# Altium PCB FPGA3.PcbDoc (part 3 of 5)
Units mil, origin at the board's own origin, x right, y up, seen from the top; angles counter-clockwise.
Board outline 4000 x 2750 mil, 12 copper layers (Top Layer, Plane1, MidLayer1, Plane2, MidLayer2, Plane3, Plane4, MidLayer 3, Plane5, MidLayer 4, Plane6, Bottom Layer), stack 57.29 mil thick; 420 components, 368 nets, 1889 pads, 1236 vias.
Unrouted connection lines stored in the file: 1.
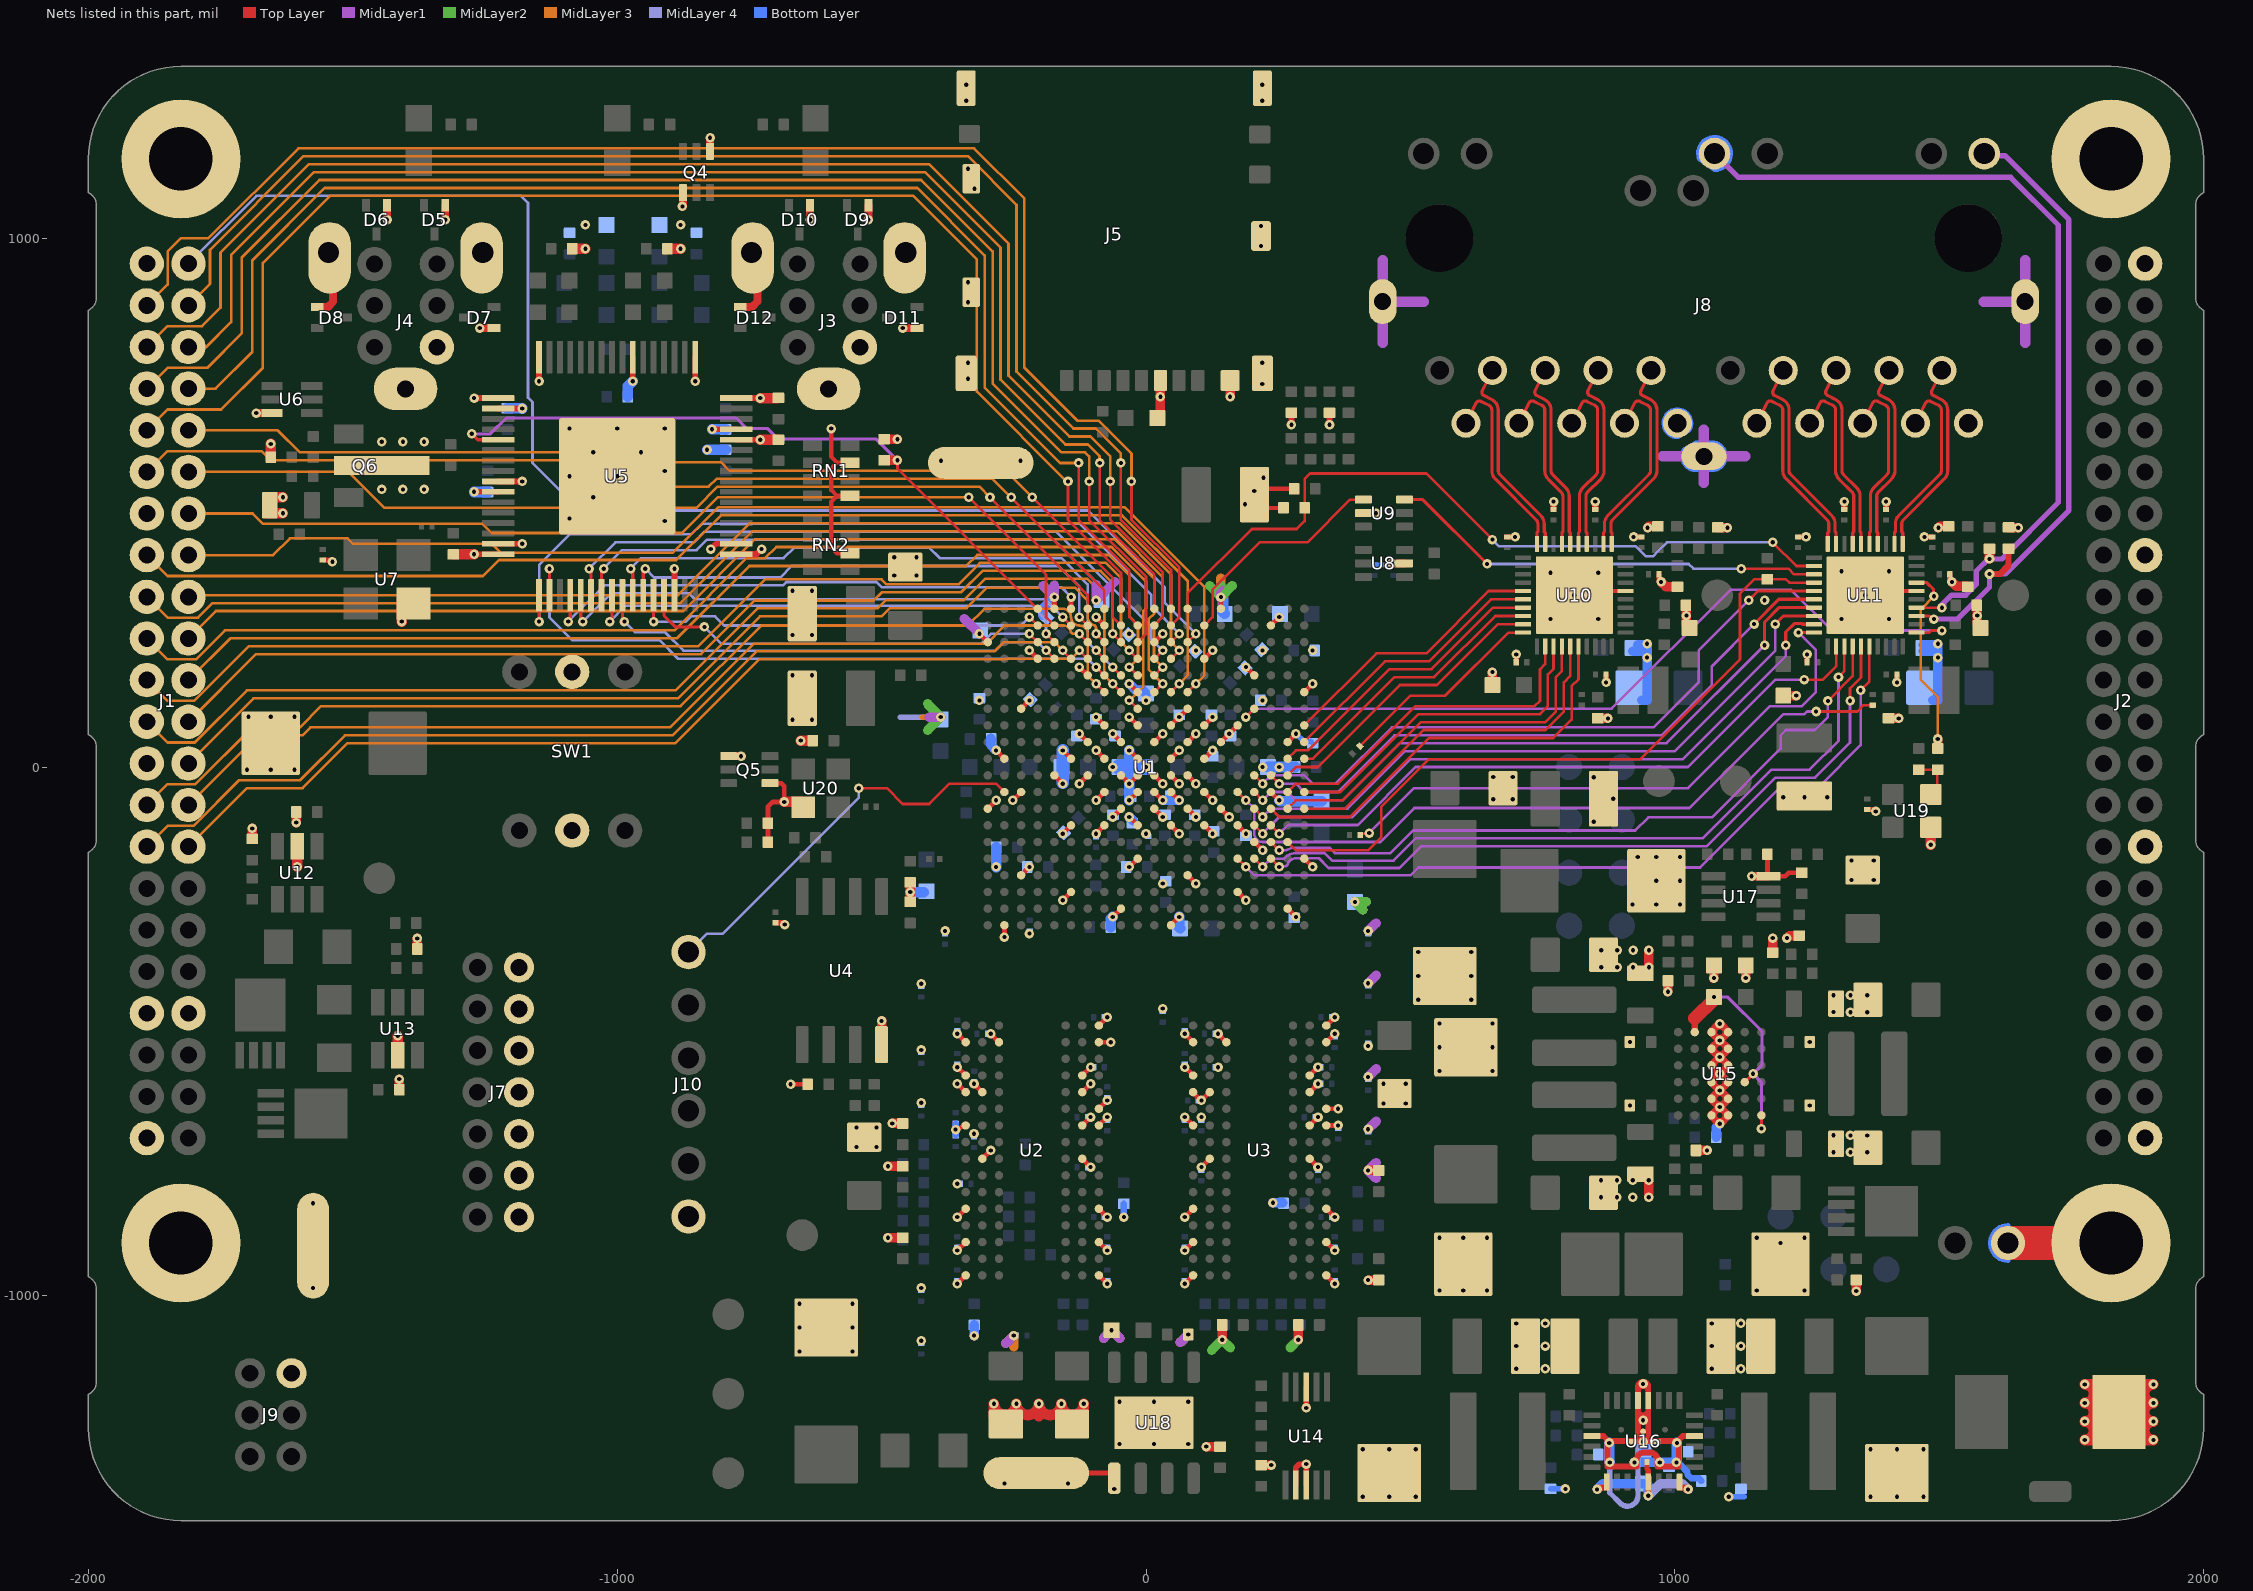
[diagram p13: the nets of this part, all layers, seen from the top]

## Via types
v1: diameter 18, hole 8, Top Layer to Bottom Layer, tented both sides, 1236 vias

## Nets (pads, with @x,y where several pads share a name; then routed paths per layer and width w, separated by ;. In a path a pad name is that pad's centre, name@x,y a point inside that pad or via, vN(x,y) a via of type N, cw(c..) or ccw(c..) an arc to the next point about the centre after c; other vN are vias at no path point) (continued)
e1-RxD0_5: U1.Y8 U10.25 | length 694.9
  Top Layer w5: U1.Y8@299.21,-78.74 376.26,-78.74 525,70 755,70 790,105 790,160 802.13,172.13 U10.25@802.13,228
e1-RxD1_5: U1.W8 U10.24 | length 711.1
  Top Layer w5: U1.W8@267.72,-78.74 283.46,-62.99 372.01,-62.99 520,85 755,85 775,105 775,170 786.38,181.38 U10.24@786.38,228
e1-RxD2_5: U1.Y9 U10.23 | length 645.4
  Top Layer w5: U1.Y9@299.21,-47.24 367.76,-47.24 515,100 745,100 760,115 760,175 770.63,185.63 U10.23@770.63,228
e1-RxD3_5: U1.W9 U10.22 | length 655.7
  Top Layer w5: U1.W9@267.72,-47.24 283.46,-31.5 363.5,-31.5 510,115 735,115 745,125 745,184.82 754.88,194.71 U10.22@754.88,228
e1-RxVAL_5: U1.V8 U10.26 | length 795.1
  Top Layer w5: U1.V8@236.22,-78.74 251.97,-94.49 385.51,-94.49 535,55 770,55 805,90 805,152.77 817.87,165.65 U10.26@817.87,228
e1-TxCLK_5: R1.2 U10.20 | length 397.3
  Top Layer w5: R1.2@404.57,39.57 500,135 565.87,135 685,254.13 U10.20@713,254.13
e1-TxD0_5: U1.Y11 U10.18 | length 525.6
  Top Layer w5: U1.Y11@299.21,15.75 315.75,15.75 470,170 545,170 660.63,285.63 U10.18@713,285.63
e1-TxD1_5: U1.W11 U10.17 | length 563.6
  Top Layer w5: U1.W11@267.72,15.75 283.47,31.5 306.5,31.5 460,185 540,185 656.38,301.38 U10.17@713,301.38
e1-TxD2_5: U1.Y12 U10.16 | length 525.6
  Top Layer w5: U1.Y12@299.21,47.24 451.97,200 535,200 652.13,317.13 U10.16@713,317.13
e1-TxD3_5: U1.Y13 U10.15 | length 519.1
  Top Layer w5: U1.Y13@299.21,78.74 435.47,215 530,215 647.87,332.87 U10.15@713,332.87
e1-TxEN_5: U1.W10 U10.19 | length 563.6
  Top Layer w5: U1.W10@267.72,-15.75 283.46,0 325,0 480,155 550,155 664.88,269.88 U10.19@713,269.88
e2-/IRQ: U1.U14 U11.31 | length 1519.4
  Top Layer w5: v1(188.98,94.49) U1.U14@204.72,110.24 ; U11.31@1457,254.13 1481.13,254.13 1485.13,258.13 v1(1505,258.13)
  MidLayer1 w5: v1(188.98,94.49) 204.72,110.24 880.24,110.24 1105,335 1220,335 1296.87,258.13 v1(1505,258.13)
e2-/RESET: R59.1 U1.N20 U11.12 | length 1449
  Top Layer w5: U1.N20@78.74,299.21 78.74,328.74 200,450 285,450 300,465 R59.1@300,490 300,545 310,555 530,555 v1(655,430) ; v1(1185,425) 1229.88,380.12 U11.12@1263,380.12
  MidLayer 4 w5: v1(655,430) 667.63,417.37 926.3,417.37 945.17,398.5 958.83,398.5 968.5,408.17 968.5,408.5 985,425 v1(1185,425)
e2-CLK25_5: R39.2 U11.37 | length 361.2
  Top Layer w6: U11.37@1457,348.62 1476.38,348.62 1489.27,335.73 v1@1489.27,323.73
  Top Layer w18: R39.2@1497,35 v1(1497,53)
  MidLayer 3 w5: v1(1490,323) 1465,298 1465,165 1497,133 v1(1497,53)
e2-LED1_5: J8.11B R71.2 U11.33 | length 1227.7
  Top Layer w5: U11.33@1457,285.63 1480.61,285.63 v1(1490,279.76)
  Top Layer w12: v1(1595,365) 1615,365 1631,381 R71.2@1631,413 ; R71.2@1630,413 R71.2@1630,415
  MidLayer1 w10: v1(1490,279.76) 1534.76,279.76 1595,340 v1(1595,365) 1625,365 1745,485 1745,1035 1624,1156 1589,1156 J8.11B@1585,1160
e2-LED2_5: J8.14B R70.2 U11.34 | length 1814.1
  Top Layer w5: U11.34@1457,301.38 v1(1505,301.38)
  Top Layer w18: v1(1595,393.5) R70.2@1595,413
  MidLayer1 w10: J8.14B@1075,1160 1120,1115 1635,1115 1725,1025 1725,500 1618.5,393.5 v1(1595,393.5) ; v1@1502.17,304.21 1509,311.03 ; v1@1509,301.38 1509,311.03 ; v1@1595,395.5 1570,370.5 1570,345 1550,325 1522.97,325 1517.3,319.34 1509,311.03
  Bottom Layer w10: 1046.81,1149.74 cw(c1075,1160) 1075,1130 1046.81,1149.78
e2-MDIO-C: U1.P19 U9.1 | length 430.1
  Top Layer w5: U1.P19@110.24,267.72 125.98,283.46 125.98,335.98 215,425 305,425 385.59,505.59 U9.1@411,505.59
e2-MDIO-C/1.8_5: U9.6 U11.13 | length 832.5
  Top Layer w5: v1(1125.5,375) 1215,375 1225.63,364.37 U11.13@1263,364.37
  Top Layer w6: U9.6@489,505.59 523.41,505.59 v1(645,384)
  MidLayer 4 w5: v1(645,384) 1026,384 1035,375 v1(1125.5,375)
e2-MDIO-D/1.8_5: R63.1 U1.W6 U11.14 | length 1323.6
  Top Layer w5: U1.W6@267.72,-141.73 283.46,-157.48 420.02,-157.48 445,-132.5 445,-75 535,15 935,15 1123.23,203.23 1123.23,328.23 1150,355 R63.1@1175,355 1210,355 1216.38,348.62 U11.14@1263,348.62
e2-RxCLK_5: R4.1 U1.T9 | length 1380.8
  Top Layer w5: U1.T9@173.23,-47.24 v1(188.98,-62.99) ; v1@1264.73,105.28 v1@1267.23,102.78 ; v1(1267,105) 1345,105 1357,117 R4.1@1374,117
  MidLayer1 w5: v1(188.98,-62.99) 204.72,-78.74 204.72,-125.98 ccw(c220.47,-125.98) 220.47,-141.73 443.27,-141.73 507.5,-77.5 1027.5,-77.5 1205,100 1245,100 1250,105 v1(1267,105)
e2-RxD0_5: U1.V5 U11.25 | length 1403.3
  Top Layer w5: U1.V5@236.22,-173.23 v1(251.97,-188.98) ; v1(1331.23,125.38) 1331.23,148.72 1352.13,169.61 U11.25@1352.13,228
  MidLayer1 w5: v1@253.22,-187.94 261.39,-187.94 ccw(c261.39,-180.94) 267.96,-183.33 cw(c283.47,-188.98) 283.47,-172.48 327,-172.48 345.52,-191 479,-191 520,-150 1060,-150 1190,-20 1265,-20 1331.23,46.23 v1(1331.23,125.38)
e2-RxD1_5: U1.V6 U11.24 | length 1339.3
  Top Layer w5: U1.V6@236.22,-141.73 v1(251.97,-157.48) ; v1(1289.45,125) 1336.38,171.93 U11.24@1336.38,228
  MidLayer1 w5: v1(251.97,-157.48) 265.03,-157.48 cw(c283.47,-188.98) 283.46,-152.48 346.74,-152.48 357.26,-163 462,-163 505,-120 925,-120 950,-95 1070,-95 1200,35 1200,60 1210,70 1265,70 1289.45,94.45 v1(1289.45,125)
e2-RxD2_5: U1.U5 U11.23 | length 1404.1
  Top Layer w5: U1.U5@204.72,-173.23 v1(220.47,-188.98) ; v1(1309.45,170) 1320.63,181.18 U11.23@1320.63,228
  MidLayer1 w5: v1(220.47,-188.98) 236.22,-173.23 261.74,-173.23 264.73,-170.24 cw(c283.47,-188.98) 283.47,-162.48 337.48,-162.48 352,-177 468,-177 510,-135 1052.5,-135 1182.5,-5 1255,-5 1309.45,49.45 v1(1309.45,170)
e2-RxD3_5: U1.V7 U11.22 | length 1243.8
  Top Layer w5: U1.V7@236.22,-110.24 v1(251.97,-125.98) ; v1(1244.73,165.28) 1279.73,165.28 1304.88,190.43 U11.22@1304.88,228
  MidLayer1 w5: v1(251.97,-125.98) 268.46,-109.49 400.51,-109.49 510,0 1025,0 1190.28,165.28 v1(1244.73,165.28)
e2-RxVAL_5: U1.T5 U11.26 | length 1486.6
  Top Layer w5: U1.T5@173.23,-173.23 v1(188.98,-188.98) ; v1(1351.23,145.38) 1367.87,162.03 U11.26@1367.87,228
  MidLayer1 w5: v1(188.98,-188.98) 204.73,-204.72 500.28,-204.72 515,-190 1048,-190 1203,-35 1275,-35 1351.23,41.23 v1(1351.23,145.38)
e2-TxCLK_5: R2.2 U11.20 | length 1126.3
  Top Layer w5: R2.2@405,-125.98 v1@420.75,-125.98
  Top Layer w6: v1(1233.58,254.13) U11.20@1263,254.13
  MidLayer1 w5: v1(422,-125) 507,-40 1025,-40 1180,115 1240,115 1266.5,141.5 1266.5,221.22 v1(1233.58,254.13)
e2-TxD0_5: U1.U8 U11.18 | length 1251.9
  Top Layer w5: U1.U8@204.72,-78.74 v1(220.47,-94.49)
  Top Layer w6: v1(1189.73,270.28) 1205.08,285.63 U11.18@1263,285.63
  MidLayer1 w5: v1(220.47,-94.49) 236.22,-78.74 381.26,-78.74 490,30 1000,30 1189.73,219.73 v1(1189.73,270.28)
e2-TxD1_5: U1.U9 U11.17 | length 1254.6
  Top Layer w5: U1.U9@204.72,-47.24 v1(220.47,-62.99)
  Top Layer w6: v1(1169.73,230.28) 1169.73,274.32 1196.79,301.38 U11.17@1263,301.38
  MidLayer1 w5: v1(220.47,-62.99) 236.22,-47.24 267.72,-47.24 283.46,-62.99 372.01,-62.99 480,45 984.45,45 v1(1169.73,230.28)
e2-TxD2_5: U1.V10 U11.16 | length 1211.6
  Top Layer w5: U1.V10@236.22,-15.75 v1(251.97,-31.5)
  Top Layer w6: v1(1149.73,270.28) 1196.58,317.13 U11.16@1263,317.13
  MidLayer1 w5: v1(251.97,-31.5) 283.46,-31.5 299.21,-47.24 362.76,-47.24 470,60 975,60 1070,155 1070,190.55 v1(1149.73,270.28)
e2-TxD3_5: U1.U10 U11.15 | length 1264.2
  Top Layer w5: U1.U10@204.72,-15.75 v1(220.47,-31.5)
  Top Layer w6: v1(1139.73,315.28) 1157.32,332.87 U11.15@1263,332.87
  MidLayer1 w5: v1(220.47,-31.5) 236.22,-15.75 299.28,-15.75 314.98,-31.45 358.55,-31.45 465,75 960,75 1045,160 1045,220.55 v1(1139.73,315.28)
e2-TxEN_5: U1.U7 U11.19 | length 1256.5
  Top Layer w5: U1.U7@204.72,-110.24 v1(220.47,-125.98)
  Top Layer w6: v1(1209.73,230.28) 1209.73,255.28 1225.58,271.13 1240.63,271.13 1241.88,269.88 U11.19@1263,269.88
  MidLayer1 w5: v1(220.47,-125.98) 251.97,-94.49 390.51,-94.49 500,15 1015,15 1209.73,209.73 v1(1209.73,230.28)
e-CLK25_5: R38.1 R39.1 U19.3 | length 93.5
  Top Layer w5: R38.1@1461,-5 1496,-5 U19.3@1496,-55 ; U19.3@1484,-52 U19.3@1486,-50
  Top Layer w11: U19.3@1484,-52 U19.3@1488,-48
ETH1-A+_5: J8.2A U10.1 | length 383.5
  Top Layer w6: U10.1@880.87,422 880.87,443.13 878.99,445 878.99,460 cw(c888.99,460) 881.92,467.07 959.6,544.75 ccw(c944,560.26) 966,560.26 966,675.1 ccw(c944,675.1) 953.84,694.78 938.94,702.24 cw(c942.07,708.5) 935.81,711.63 J8.2A@955,750
ETH1-A-_5: J8.3A U10.2 | length 370.2
  Top Layer w6: U10.2@865.12,422 865.12,443.13 866.99,445 866.99,460 cw(c888.99,460) 873.4,475.52 ; J8.3A@905,650 924.19,688.37 cw(c930.45,685.24) 933.58,691.5 948.47,684.04 cw(c944,675.1) 954,675.1 954,560.26 cw(c944,560.26) 951.07,553.19 873.44,475.56 ; 873.4,475.52 cw(c888.99,460) 873.44,475.56 ; 873.4,475.52 873.44,475.56
ETH1-B+_5: J8.4A U10.4 | length 361.6
  Top Layer w6: U10.4@833.62,422 833.62,443.13 831.75,445 831.75,512.49 cw(c841.75,512.49) 834.68,519.56 859.6,544.48 ccw(c844,560) 866,560 866,675.1 ccw(c844,675.1) 853.84,694.78 838.94,702.24 cw(c842.07,708.5) 835.81,711.63 J8.4A@855,750
ETH1-B-_5: J8.5A U10.5 | length 348.3
  Top Layer w6: J8.5A@805,650 824.19,688.37 cw(c830.45,685.24) 833.58,691.5 848.47,684.04 cw(c844,675.1) 854,675.1 854,560 cw(c844,560) 851.07,552.93 826.15,528.01 ccw(c841.75,512.49) 819.75,512.49 819.75,445 817.87,443.13 U10.5@817.87,422
ETH1-C+_5: J8.6A U10.6 | length 361.6
  Top Layer w6: J8.6A@755,750 735.81,711.63 ccw(c742.07,708.5) 738.94,702.24 753.84,694.78 cw(c744,675.1) 766,675.1 766,560 ccw(c776,560) 768.93,552.93 793.85,528.01 cw(c778.25,512.49) 800.25,512.49 800.25,445 802.13,443.13 U10.6@802.13,422
ETH1-C-_5: J8.7A U10.7 | length 348.3
  Top Layer w6: J8.7A@705,650 724.19,688.37 cw(c730.45,685.24) 733.58,691.5 748.47,684.04 cw(c744,675.1) 754,675.1 754,560 ccw(c776,560) 760.4,544.48 785.32,519.56 cw(c778.25,512.49) 788.25,512.49 788.25,445 786.38,443.13 U10.7@786.38,422
ETH1-D+_5: J8.8A U10.9 | length 383.4
  Top Layer w6: J8.8A@655,750 635.81,711.63 ccw(c642.07,708.5) 638.94,702.24 653.84,694.78 cw(c644,675.1) 666,675.1 666,560.26 ccw(c676,560.26) 668.93,553.19 746.56,475.56 ; 746.6,475.52 cw(c731.01,460) 753.01,460 753.01,445 754.88,443.13 U10.9@754.88,422
ETH1-D-_5: J8.9A U10.10 | length 370.2
  Top Layer w6: J8.9A@605,650 624.19,688.37 cw(c630.45,685.24) 633.58,691.5 648.47,684.04 cw(c644,675.1) 654,675.1 654,560.26 ccw(c676,560.26) 660.4,544.75 738.08,467.07 cw(c731.01,460) 741.01,460 741.01,445 739.13,443.13 U10.10@739.13,422
ETH2-A+_5: J8.2B U11.1 | length 383.5
  Top Layer w6: U11.1@1430.87,422 1430.87,443.13 1428.99,445 1428.99,460 cw(c1438.99,460) 1431.92,467.07 1509.6,544.75 ccw(c1494,560.26) 1516,560.26 1516,675.1 ccw(c1494,675.1) 1503.84,694.78 1488.94,702.24 cw(c1492.07,708.5) 1485.81,711.63 J8.2B@1505,750
ETH2-A-_5: J8.3B U11.2 | length 370.2
  Top Layer w6: U11.2@1415.12,422 1415.12,443.13 1416.99,445 1416.99,460 cw(c1438.99,460) 1423.4,475.52 ; J8.3B@1455,650 1474.19,688.37 cw(c1480.45,685.24) 1483.58,691.5 1498.47,684.04 cw(c1494,675.1) 1504,675.1 1504,560.26 cw(c1494,560.26) 1501.07,553.19 1423.44,475.56 ; 1423.4,475.52 cw(c1438.99,460) 1423.44,475.56 ; 1423.4,475.52 1423.44,475.56
ETH2-B+_5: J8.4B U11.4 | length 361.6
  Top Layer w6: U11.4@1383.62,422 1383.62,443.13 1381.75,445 1381.75,512.49 cw(c1391.75,512.49) 1384.68,519.56 1409.6,544.48 ccw(c1394,560) 1416,560 1416,675.1 ccw(c1394,675.1) 1403.84,694.78 1388.94,702.24 cw(c1392.07,708.5) 1385.81,711.63 J8.4B@1405,750
ETH2-B-_5: J8.5B U11.5 | length 348.3
  Top Layer w6: J8.5B@1355,650 1374.19,688.37 cw(c1380.45,685.24) 1383.58,691.5 1398.47,684.04 cw(c1394,675.1) 1404,675.1 1404,560 cw(c1394,560) 1401.07,552.93 1376.15,528.01 ccw(c1391.75,512.49) 1369.75,512.49 1369.75,445 1367.87,443.13 U11.5@1367.87,422
ETH2-C+_5: J8.6B U11.6 | length 361.6
  Top Layer w6: J8.6B@1305,750 1285.81,711.63 ccw(c1292.07,708.5) 1288.94,702.24 1303.84,694.78 cw(c1294,675.1) 1316,675.1 1316,560 ccw(c1326,560) 1318.93,552.93 1343.85,528.01 cw(c1328.25,512.49) 1350.25,512.49 1350.25,445 1352.13,443.13 U11.6@1352.13,422
ETH2-C-_5: J8.7B U11.7 | length 348.3
  Top Layer w6: J8.7B@1255,650 1274.19,688.37 cw(c1280.45,685.24) 1283.58,691.5 1298.47,684.04 cw(c1294,675.1) 1304,675.1 1304,560 ccw(c1326,560) 1310.4,544.48 1335.32,519.56 cw(c1328.25,512.49) 1338.25,512.49 1338.25,445 1336.38,443.13 U11.7@1336.38,422
ETH2-D+_5: J8.8B U11.9 | length 383.4
  Top Layer w6: J8.8B@1205,750 1185.81,711.63 ccw(c1192.07,708.5) 1188.94,702.24 1203.84,694.78 cw(c1194,675.1) 1216,675.1 1216,560.26 ccw(c1226,560.26) 1218.93,553.19 1296.56,475.56 ; 1296.6,475.52 cw(c1281.01,460) 1303.01,460 1303.01,445 1304.88,443.13 U11.9@1304.88,422
ETH2-D-_5: J8.9B U11.10 | length 370.2
  Top Layer w6: J8.9B@1155,650 1174.19,688.37 cw(c1180.45,685.24) 1183.58,691.5 1198.47,684.04 cw(c1194,675.1) 1204,675.1 1204,560.26 ccw(c1226,560.26) 1210.4,544.75 1288.08,467.07 cw(c1281.01,460) 1291.01,460 1291.01,445 1289.13,443.13 U11.10@1289.13,422
FW-/RST: R83.1 U1.D20 U5.53 | length 1320.8
  Top Layer w5: v1(-470,580) -470,564.49 U1.D20@-204.72,299.21
  Top Layer w6: v1(-1275,630) -1263.9,618.9 U5.53@-1225,618.9
  Top Layer w18: R83.1@-495,580 v1(-470,580)
  MidLayer1 w6: v1(-1275,630) -1240,630 -1210,660 -775,660 -755,640 -715,640 -695,620 -510,620 v1(-470,580)
FW-CLK: U1.H16 U5.2 | length 1236.7
  Top Layer w5: v1(-94.49,188.98) U1.H16@-78.74,173.23
  Top Layer w6: U5.2@-1127.95,325 v1(-1127.95,375)
  MidLayer 4 w5: v1(-1127.95,375) -1127.95,282.95 -1085,240 -920,240 -884.75,204.75 -110.26,204.75 v1(-94.49,188.98)
FW-CTL0: U1.F20 U5.4 | length 1067.7
  Top Layer w6: v1(-1092.58,275) -1088.58,279 U5.4@-1088.58,325
  Top Layer w9: U1.F20@-141.73,299.21 v1(-141.73,321.48)
  MidLayer 4 w5: v1(-1092.58,275) -1024.08,343.5 -686.5,343.5 -680,350 -510,350 -500,340 -160.25,340 v1(-141.73,321.48)
FW-CTL1: U1.F19 U5.5 | length 1022.2
  Top Layer w5: v1(-157.48,283.46) U1.F19@-141.73,267.72
  Top Layer w6: U5.5@-1068.9,325 -1068.9,279 v1(-1064.9,275)
  MidLayer 4 w5: v1(-1064.9,275) -1011.4,328.5 -864,328.5 -852.5,317 -191.02,317 v1(-157.48,283.46)
FW-D0: U1.L17 U5.6 | length 1294.1
  Top Layer w5: U1.L17@15.75,204.72 v1(31.5,220.47)
  Top Layer w6: v1(-1053.21,375) -1049.21,371 U5.6@-1049.21,325
  MidLayer 4 w5: v1(-1053.21,375) -1003.21,425 -855,425 -835,445 -170,445 10,265 10,241.97 v1(31.5,220.47)
FW-D1: U1.J16 U5.7 | length 1234.7
  Top Layer w5: v1(-62.99,188.98) U1.J16@-47.24,173.23
  Top Layer w6: U5.7@-1029.53,325 -1029.53,371 v1(-1025.53,375)
  MidLayer 4 w5: v1(-1025.53,375) -990.53,410 -850,410 -830,430 -175,430 -78.74,333.74 -78.74,204.72 v1(-62.99,188.98)
FW-D2: U1.E18 U5.8 | length 948.4
  Top Layer w5: v1(-188.98,251.97) U1.E18@-173.23,236.22
  Top Layer w6: v1(-1013.84,275) -1009.84,279 U5.8@-1009.84,325
  MidLayer 4 w5: v1(-1013.84,275) -983.84,305 -216,305 -188.98,277.97 v1(-188.98,251.97)
FW-D3: U1.E17 U5.9 | length 907.1
  Top Layer w5: v1(-188.98,220.47) U1.E17@-173.23,204.72
  Top Layer w6: U5.9@-990.16,325 -990.16,279 v1(-986.16,275)
  MidLayer 4 w5: v1(-986.16,275) -966.16,255 -910,255 -875,220 -285,220 -268.78,236.22 -204.72,236.22 v1(-188.98,220.47)
FW-D4: U1.H17 U5.10 | length 1114.9
  Top Layer w5: v1(-94.49,220.47) U1.H17@-78.74,204.72
  Top Layer w6: v1(-974.47,375) -970.47,371 U5.10@-970.47,325
  MidLayer 4 w5: v1(-974.47,375) -954.47,395 -685,395 -665,415 -410,415 -390,395 -160,395 -110.24,345.24 -110.24,236.22 v1(-94.49,220.47)
FW-D5: U1.G19 U5.11 | length 1009.4
  Top Layer w5: v1(-125.98,283.46) U1.G19@-110.24,267.72
  Top Layer w6: U5.11@-950.79,299.79 U5.11@-950.79,325 -950.79,371 v1(-946.79,375)
  MidLayer 4 w5: v1(-946.79,375) -930.29,358.5 -691.5,358.5 -670,380 -165,380 -125.98,340.98 v1(-125.98,283.46)
FW-D6: U1.D19 U5.12 | length 800.7
  Top Layer w5: v1(-220.47,283.46) U1.D19@-204.72,267.72
  Top Layer w6: v1(-931.1,275) U5.12@-931.1,325
  MidLayer 4 w5: v1(-931.1,275) -870,275 -860,285 -815,285 -797.72,267.72 -236.22,267.72 v1(-220.47,283.46)
FW-D7: U1.D18 U5.13 | length 781.8
  Top Layer w5: v1(-220.47,251.97) U1.D18@-204.72,236.22
  Top Layer w6: U5.13@-911.42,325 -911.42,286.42 -890,265 v1(-835,265)
  MidLayer 4 w5: v1(-835,265) -803,233 -312,233 -293.03,251.97 v1(-220.47,251.97)
FW-LREQ: U1.M18 U5.1 | length 1520.3
  Top Layer w5: U1.M18@47.24,236.22 v1(62.99,251.97)
  Top Layer w6: v1(-1147.64,275) U5.1@-1147.64,325
  MidLayer 4 w5: v1(-1147.64,275) -1147.64,382.36 -1090,440 -860,440 -840,460 -125,460 10,325 10,304.96 v1(62.99,251.97)
GND: C6.2 C7.2 C8.2 C9.2 C11.2 C12.2 C13.2 C14.2 C15.2 C16.2 C17.2 C18.2 C19.2 C20.2 C21.2 C22.2 C25.2 C26.2 C27.2 C28.2 C29.2 C30.2 C31.2 C32.2 C33.2 C34.2 C35.2 C36.2 C37.2 C38.2 C39.2 C40.2 C41.2 C42.2 C43.2 C44.2 C45.2 C46.2 C47.2 C48.2 C49.2 C50.2 C51.2 C52.2 C53.2 C54.2 C55.2 C56.2 C57.2 C58.2 C59.2 C60.2 C61.2 C62.2 C63.2 C64.2 C65.2 C66.2 C67.2 C68.2 C69.2 C70.2 C71.2 C72.2 C73.2 C74.2 C75.2 C76.2 C77.2 C78.2 CB1.2 CB2.2 CB3.2 CB4.2 CB5.2 CB6.2 CB7.2 CB8.2 CB9.2 CB10.2 CB11.2 CB12.2 CB13.2 CB14.2 CB15.2 CB16.2 CB17.2 CB18.2 CB19.2 CB20.2 CB21.2 CB22.2 CB23.2 CB24.2 CB25.2 CB26.2 CB27.2 CB28.2 CB29.2 CB30.2 CB31.2 CB32.2 CB33.2 CB34.2 CB35.2 CB36.2 CB37.2 CB38.2 CB39.2 CB40.2 CB41.2 CB42.2 CB43.2 CB44.2 CB45.2 CB46.2 CB47.2 CB48.2 CB49.2 CB50.2 CB51.2 CB52.2 CB53.2 CB54.2 CB55.2 CB56.2 CB57.2 CB58.2 CB59.2 CB60.2 CB61.2 CB62.2 CB63.2 CB64.2 CB65.2 CB66.2 CB67.2 CB68.2 CB69.2 CB70.2 CB71.2 CB72.2 CB73.2 CB74.2 CB75.2 CB76.2 CB77.2 CB78.2 CB79.2 CB80.2 CB81.2 CB82.2 CB83.2 CB84.2 CB85.2 CB86.2 CB87.2 CB88.2 CB89.2 CB90.2 CB91.2 CB92.2 CB93.2 CB94.2 CB95.2 CB96.2 CB97.2 CB98.2 CB99.2 CB100.2 CB101.2 CB102.2 CB103.2 CB104.2 CB105.2 CB106.2 CB107.2 CB108.2 CB109.2 CB110.2 CB111.2 CB112.2 CB113.2 CB114.2 CB115.2 CB116.2 CB117.2 CB118.2 CB119.2 CB120.2 CB121.2 CB122.2 CB123.2 CB124.2 CB125.2 CB126.2 CB127.2 CB128.2 CB129.2 CB130.2 CB131.2 CB132.2 CB133.2 CB134.2 CB135.2 CB136.2 CB137.2 CB138.2 CB139.2 CB140.2 D1.2 D5.1 D6.1 D7.1 D8.1 D9.1 D10.1 D11.1 D12.1 J1.2 J1.14 J1.26 J1.37 J1.38 J1.44 J2.1 J2.15 J2.29 J2.43 J3.2 J3.7 J3.8 J3.9 J4.2 J4.7 J4.8 J4.9 J5.6 J5.12 J5.13 J5.14 J5.15 J5.16 J5.17 J5.18 J5.19 J6.2 J7.1 J7.3 J7.5 J7.7 J7.9 J7.11 J7.13 J8.1 J8.1A J8.1B J8.2 J8.3 J9.1 J10.1 M1.1 M2.1 M3.1 M4.1 pad.0@-207.5,-1335 pad.0@-312.5,575 pad.0@-1575,-905 Q4.1 Q4.4 Q5.1 Q5.4 Q6.3 R33.2 R40.2 R42.2 R44.2 R45.2 R58.2 R59.2 R60A.2 R65.2 R66.2 R69.1 R71.1 R73.2 R75.2 R76.2 R77.2 R80.2 R81.2 R82.2 R83.2 R84.1 R85.1 R88.1 R89.1 R90.1 R92.2 R96.2 R97.2 R99.2 R101.2 R105.2 R106.2 RN1.1 RN1.3 RN2.2 SW1.2 SW1.5 U1.A8 U1.A18 U1.B1 U1.B11 U1.C4 U1.C9 U1.C14 U1.D17 U1.E10 U1.E20 U1.F3 U1.F7 U1.F11 U1.G10 U1.G12 U1.G16 U1.H7 U1.H9 U1.H11 U1.H13 U1.H19 U1.J2 U1.J8 U1.J10 U1.J12 U1.K5 U1.K7 U1.K9 U1.K10 U1.K11 U1.K13 U1.K15 U1.L8 U1.L9 U1.L10 U1.L12 U1.L18 U1.M1 U1.M7 U1.M9 U1.M10 U1.M11 U1.M13 U1.N4 U1.N8 U1.N10 U1.N12 U1.N14 U1.P7 U1.P9 U1.P11 U1.P13 U1.P17 U1.R8 U1.R12 U1.R20 U1.T3 U1.T7 U1.T13 U1.U6 U1.U16 U1.V9 U1.V19 U1.W2 U1.W12 U1.Y5 U1.Y15 U2.A9 U2.B1 U2.B3 U2.B9 U2.D1 U2.D8 U2.E1 U2.E2 U2.E8 U2.F9 U2.G1 U2.G8 U2.G9 U2.J2 U2.J8 U2.M1 U2.M9 U2.P1 U2.P9 U2.T1 U2.T9 U3.A9 U3.B1 U3.B3 U3.B9 U3.D1 U3.D8 U3.E1 U3.E2 U3.E8 U3.F9 U3.G1 U3.G8 U3.G9 U3.J2 U3.J8 U3.M1 U3.M9 U3.P1 U3.P9 U3.T1 U3.T9 U4.4 U5.14 U5.17 U5.18 U5.28 U5.29 U5.32 U5.33 U5.39 U5.48 U5.49 U5.50 U5.57 U5.58 U5.63 U5.64 U5.65 U6.6 U7.2 U8.2 U9.2 U10.36 U10.41 U11.36 U11.41 U12.2 U13.2 U14.2 U14.3 U14.8 U15.A3 U15.A4 U15.B3 U15.B4 U15.C3 U15.C4 U15.D3 U15.D4 U15.E3 U15.E4 U15.F3 U15.F4 U16.12 U16.18 U16.19 U16.25 U16.30 U16.31 U16.32 U17.4 U18.1 U18.9 U19.2 U20.2 | length 13940.1
  Top Layer w6: U15.F4@1093.1,-658.74 ccw(c1085,-658.74) U15.F4@1093.1,-658.74 ; U15.E4@1093.1,-627.24 ccw(c1085,-627.24) U15.E4@1093.1,-627.24 ; U15.D4@1093.1,-595.75 ccw(c1085,-595.75) U15.D4@1093.1,-595.75 ; U15.C4@1093.1,-564.25 ccw(c1085,-564.25) U15.C4@1093.1,-564.25 ; U15.B4@1093.1,-532.76 ccw(c1085,-532.76) U15.B4@1093.1,-532.76 ; U15.A4@1093.1,-501.26 ccw(c1085,-501.26) U15.A4@1093.1,-501.26
  Top Layer w8: CB75.2@-701,-295 CB75.2@-700.5,-294.5 ; v1(-672,-600) R90.1@-640,-600 ; v1(-595,640) -595,586.5 -584.25,575.75 ; RN2.2@-559.5,404.25 -584.25,404.25 -595,415 -595,502.01 -584.25,512.76 ; RN1.1@-559.5,512.76 -584.25,512.76 ; RN1.3@-559.5,575.75 -584.25,575.75 ; C47.2@-533,-697 C47.2@-530,-700 ; J5.17@-348.66,1255 J5.17@-340,1263.66 ; R59.2@260,490 228.5,490 205,513.5 C62.2@205,515 216,526 R58.2@280,526 ; v1(810,325) 817.87,332.87 U10.36@907,332.87 ; v1(1360,325) 1367.87,332.87 U11.36@1457,332.87 ; -584.25,512.76 -595,523.5 -595,565 -584.25,575.75
  Top Layer w9: R85.1@-715,-142 R84.1@-715,-106 -715,-75 -706,-66 v1(-684,-66) -684,-36 -689.27,-30.73 -712.36,-30.73 Q5.1@-712.5,-30.59 ; v1(-360,-685.5) U2.G1@-340.98,-677.76 ; v1(-356.73,-976.97) U2.T1@-340.98,-961.22 ; v1(-356.73,-913.98) U2.P1@-340.98,-898.23 ; v1(-356.73,-850.98) U2.M1@-340.98,-835.24 ; v1(-356.73,-599.02) U2.E1@-340.98,-614.76 ; v1(-356.73,-567.52) U2.D1@-340.98,-583.27 ; v1(-356.73,-504.53) U2.B1@-340.98,-520.28 ; v1(-325.24,-599.02) U2.E2@-309.49,-614.76 ; v1(-314.96,251.97) U1.A18@-299.21,236.22 ; U2.J2@-309.49,-740.75 v1(-293.74,-725) ; U1.A8@-299.21,-78.74 v1(-283.46,-62.99) ; v1(-293.74,-504.53) U2.B3@-277.99,-520.28 ; v1(-283.46,31.5) U1.B11@-267.72,15.75 ; v1(-267.72,-321.48) U1.B1@-267.72,-299.21 ; v1(-251.97,-62.99) U1.C9@-236.22,-47.24 ; U1.C4@-236.22,-204.72 v1(-220.47,-188.98) ; U1.C14@-236.22,110.24 v1(-220.47,125.98) ; v1(-220.47,220.47) U1.D17@-204.72,204.72 ; U1.E10@-173.23,-15.75 v1(-157.48,-31.5) ; U1.E20@-173.23,299.21 v1(-173.23,321.48) ; v1(-157.48,-251.97) U1.F3@-141.73,-236.22 ; v1(-157.48,-125.98) U1.F7@-141.73,-110.24 ; v1(-157.48,31.5) U1.F11@-141.73,15.75 ; v1(-125.98,-31.5) U1.G10@-110.24,-15.75 ; v1(-125.98,62.99) U1.G12@-110.24,47.24 ; v1(-125.98,188.98) U1.G16@-110.24,173.23 ; U2.J8@-120.51,-740.75 v1(-104.76,-756.5) ; U2.G8@-120.51,-677.76 v1(-104.76,-662.01) ; U2.E8@-120.51,-614.76 v1(-104.76,-599.02) ; U2.D8@-120.51,-583.27 v1(-104.76,-567.52) ; v1(-94.49,-125.98) U1.H7@-78.74,-110.24 ; v1(-94.49,-62.99) U1.H9@-78.74,-47.24 ; v1(-94.49,31.5) U1.H11@-78.74,15.75 ; v1(-94.49,94.49) U1.H13@-78.74,78.74 ; v1(-94.49,283.46) U1.H19@-78.74,267.72 ; U2.T9@-89.02,-961.22 v1(-73.27,-976.97) ; U2.P9@-89.02,-898.23 v1(-73.27,-913.98) ; U2.M9@-89.02,-835.24 v1(-73.27,-850.98) ; U2.G9@-89.02,-677.76 v1(-73.27,-662.01) ; U2.F9@-89.02,-646.26 v1(-73.27,-630.51) ; U2.B9@-89.02,-520.28 v1(-66.74,-520.28) ; U2.A9@-89.02,-488.78 v1(-73.27,-473.03) ; v1(-62.99,-283.46) U1.J2@-47.24,-267.72 ; v1(-62.99,-94.49) U1.J8@-47.24,-78.74 ; v1(-62.99,62.99) U1.J12@-47.24,47.24 ; U1.J10@-47.24,-15.75 v1(-31.5,-31.5) U1.K10@-15.75,-15.75 ; v1(-31.5,-188.98) U1.K5@-15.75,-173.23 ; v1(-31.5,-94.49) U1.K7@-15.75,-110.24 ; v1(-31.5,-62.99) U1.K9@-15.75,-47.24 ; v1(-31.5,31.5) U1.K11@-15.75,15.75 ; v1(-31.5,94.49) U1.K13@-15.75,78.74 ; v1(-31.5,157.48) U1.K15@-15.75,141.73 ; U1.L8@15.75,-78.74 v1(31.5,-94.49) ; U1.L9@15.75,-47.24 v1(31.5,-62.99) ; U1.L10@15.75,-15.75 v1(31.5,-31.5) ; U1.L12@15.75,47.24 v1(31.5,62.99) ; U1.L18@15.75,236.22 v1(31.5,251.97) ; U1.M1@47.24,-299.21 v1(62.99,-283.46) ; U1.M7@47.24,-110.24 v1(62.99,-125.98) ; U1.M9@47.24,-47.24 v1(62.99,-62.99) ; U1.M10@47.24,-15.75 v1(62.99,-31.5) ; U1.M11@47.24,15.75 v1(62.99,31.5) ; U1.M13@47.24,78.74 v1(62.99,94.49) U1.N14@78.74,110.24 ; v1(73.27,-976.97) U3.T1@89.02,-961.22 ; v1(73.27,-913.98) U3.P1@89.02,-898.23 ; v1(73.27,-850.98) U3.M1@89.02,-835.24 ; v1(73.27,-662.01) U3.G1@89.02,-677.76 ; v1(73.27,-567.52) U3.D1@89.02,-583.27 ; v1(73.27,-504.53) U3.B1@89.02,-520.28 ; U1.N4@78.74,-204.72 v1(94.49,-220.47) ; U1.N8@78.74,-78.74 v1(94.49,-94.49) ; U1.N10@78.74,-15.75 v1(94.49,-31.5) ; U1.N12@78.74,47.24 v1(94.49,62.99) ; U3.E1@87.28,-613.78 v1@103.03,-629.53 ; v1(104.76,-756.5) U3.J2@120.51,-740.75 ; v1(104.76,-630.51) U3.E2@120.51,-614.76 ; U1.P7@110.24,-110.24 v1(125.98,-125.98) ; U1.P9@110.24,-47.24 v1(125.98,-62.99) ; U1.P11@110.24,15.75 v1(125.98,31.5) ; U1.P13@110.24,78.74 v1(125.98,94.49) ; U1.P17@110.24,204.72 v1(125.98,220.47) ; v1(136.26,-504.53) U3.B3@152.01,-520.28 ; U1.R8@141.73,-78.74 v1(157.48,-94.49) ; U1.R12@141.73,47.24 v1(157.48,62.99) U1.T13@173.23,78.74 ; U1.R20@141.73,299.21 v1(141.73,321.48) ; U1.T3@173.23,-236.22 v1(188.98,-251.97) ; U1.T7@173.23,-110.24 v1(188.98,-125.98) ; v1(188.98,188.98) U1.U16@204.72,173.23 ; U1.U6@204.72,-141.73 v1(220.47,-157.48) ; U1.V9@236.22,-47.24 v1(251.97,-62.99) ; U1.V19@236.22,267.72 v1(251.97,283.46) ; U1.W2@267.72,-267.72 v1(283.46,-283.46) ; U1.W12@267.72,47.24 v1(283.46,62.99) ; U1.Y5@299.21,-173.23 v1(314.96,-188.98) ; U1.Y15@299.21,141.73 v1(314.96,157.48) ; U3.J8@309.49,-740.75 v1(325.24,-756.5) ; U3.G8@309.49,-677.76 v1(325.24,-662.01) ; U3.E8@309.49,-614.76 v1(325.24,-599.02) ; U3.D8@309.49,-583.27 v1(325.24,-567.52) ; U3.T9@340.98,-961.22 v1(356.73,-976.97) ; U3.P9@340.98,-898.23 v1(356.73,-913.98) ; U3.M9@340.98,-835.24 v1(356.73,-850.98) ; U3.G9@340.98,-677.76 v1(363.26,-677.76) ; U3.F9@340.98,-646.26 v1(363.26,-646.26) ; U3.B9@340.98,-520.28 v1(356.73,-504.53) ; U3.A9@340.98,-488.78 v1(356.73,-473.03) ; R105.2@1175,-165 1175,-204.61 U17.4@1177,-206.61 1208.39,-206.61 1215,-200 R80.2@1240,-200
  Top Layer w10: CB74.2@-1554.29,391.5 v1@-1539.29,391.5 ; CB75.2@-698.92,-294.5 v1@-683.92,-294.5 ; pad.0@-147.5,-1335 U18.1@-67.5,-1335 ; CB59.2@684,435 v1(698,435) ; CB51.2@700,199 v1(700,213) ; v1(870,160) CB49.2@870,174 ; v1(922,435) CB55.2@936,435 ; v1@970,350 CB53.2@970,364 ; CB56.2@1234,435 v1(1248,435) ; CB52.2@1250,199 v1(1250,213) ; CB73.2@1364,-80.5 v1@1379,-80.5 ; v1(1420,160) CB50.2@1420,174 ; v1(1472,435) CB60.2@1486,435 ; v1@1520,350 CB54.2@1520,364
  Top Layer w11: v1(-1270.47,402.36) U5.64@-1225,402.36 ; v1(-1270.47,520.47) U5.58@-1225,520.47 ; v1(-1270.47,697.64) U5.49@-1225,697.64 ; U5.63@-1225,422.05 v1(-1179.53,422.05) ; U5.57@-1225,540.16 v1(-1179.53,540.16) ; U5.50@-1225,677.95 v1(-1179.53,677.95) ; v1(-1147.64,729.53) U5.48@-1147.64,775 ; v1(-970.47,729.53) U5.39@-970.47,775 ; U5.14@-891.73,325 v1(-891.73,375) ; v1(-852.36,729.53) U5.33@-852.36,775 ; v1(-823,412.2) -813.16,422.05 U5.18@-775,422.05 ; v1(-820.47,638.58) U5.29@-775,638.58 ; U5.28@-775,618.9 v1(-729.53,618.9) ; U5.32@-775,697.64 v1(-729.53,697.64) ; U14.2@283.31,-1357.5 283.31,-1324.69 289.47,-1318.53 302.47,-1318.53 v1(303,-1318) U14.3@303,-1357.5 ; v1(303,-1212) U14.8@303,-1172.5 ; U16.25@843,-1265.16 865,-1265.16 v1@874.34,-1274.5 ; v1@872.53,-1274.5 872.53,-1322.47 928,-1322.47 v1@928,-1310.06 ; v1@876,-1274.5 930.16,-1274.5 ; v1@928,-1310 cw(c942,-1310.06) 942,-1296.06 953,-1296.06 cw(c953,-1310.06) v1@967,-1310 ; 930.16,-1275 930.16,-1274.5 ; 930.16,-1216 ccw(c940,-1216) 949.84,-1216.06 ; 930.16,-1180 cw(c940,-1180) 949.84,-1179.96 ; 949.84,-1275 949.84,-1274.5 ; 949.84,-1216 cw(c940,-1216) 949.84,-1216.06 ; v1@967,-1310.06 967,-1322.47 1007.47,-1322.47 v1@1007.47,-1274.5 ; v1@1004,-1274.5 949.84,-1274.5 ; v1@1005.66,-1274.5 1015,-1265.16 U16.12@1037,-1265.16 ; 930.16,-1274.5 U16.19@930.16,-1198 930.16,-1172.5 cw(c940,-1172.5) 949.84,-1172.5 949.84,-1179.96 ; 930.16,-1274.5 949.84,-1274.5 ; 949.84,-1274.5 949.84,-1216.06 ; 949.84,-1216.06 U16.18@949.84,-1198 949.84,-1179.97
  Top Layer w11.5: U5.17@-775,402.36 -736.84,402.36 v1(-727,412.2)
  Top Layer w12: v1(275,647) R40.2@275,670 ; v1(347,647) R42.2@347,670 ; CB57.2@770.63,488 v1(770.63,502) ; CB61.2@849.37,488 v1(849.37,502) ; CB58.2@1320.63,488 v1(1320.63,502) ; CB62.2@1399.37,488 v1(1399.37,502)
  Top Layer w14: U15.F3@1068.54,-659.45 v1@1084.29,-675.19 ; U15.F3@1068.54,-658.03 v1@1083.59,-642.99 ; U15.E3@1068.54,-627.95 v1@1083.59,-642.99 ; U15.E3@1068.54,-626.54 v1@1083.59,-611.5 ; U15.D3@1068.55,-596.46 v1@1083.59,-611.5 ; U15.D3@1068.54,-595.04 v1@1083.59,-580 ; U15.C3@1068.55,-564.96 v1@1083.59,-580 ; U15.C3@1068.54,-563.54 v1@1083.59,-548.5 ; U15.B3@1068.54,-533.46 v1@1083.59,-548.5 ; U15.B3@1068.54,-532.05 v1@1083.59,-517.01 ; U15.A3@1068.55,-501.97 v1@1083.59,-517.01 ; U15.A3@1068.55,-500.55 v1@1084.29,-484.8 ; v1@1084.29,-643.7 v1@1083.59,-642.99 ; v1@1084.29,-642.29 v1@1083.59,-642.99 ; v1@1084.29,-612.2 v1@1083.59,-611.5 ; v1@1084.29,-610.79 v1@1083.59,-611.5 ; v1@1084.29,-580.71 v1@1083.59,-580 ; v1@1084.29,-579.29 v1@1083.59,-580 ; v1@1084.29,-549.21 v1@1083.59,-548.5 ; v1@1084.29,-547.8 v1@1083.59,-548.5 ; v1@1084.29,-517.71 v1@1083.59,-517.01 ; v1@1084.29,-516.3 v1@1083.59,-517.01 ; v1@1085.71,-675.19 U15.F4@1101.45,-659.45 ; v1@1085.71,-643.7 v1@1086.41,-642.99 ; v1@1085.71,-642.29 v1@1086.41,-642.99 ; v1@1085.71,-612.2 v1@1086.41,-611.5 ; v1@1085.71,-610.79 v1@1086.41,-611.5 ; v1@1085.71,-580.71 v1@1086.41,-580 ; v1@1085.71,-579.29 v1@1086.41,-580 ; v1@1085.71,-549.21 v1@1086.41,-548.5 ; v1@1085.71,-547.8 v1@1086.41,-548.5 ; v1@1085.71,-517.71 v1@1086.41,-517.01 ; v1@1085.71,-516.3 v1@1086.41,-517.01 ; v1@1085.71,-484.8 U15.A4@1101.46,-500.55 ; U15.F4@1101.45,-658.03 v1@1086.41,-642.99 ; U15.E4@1101.45,-627.95 v1@1086.41,-642.99 ; U15.E4@1101.45,-626.54 v1@1086.41,-611.5 ; U15.D4@1101.45,-596.45 v1@1086.41,-611.5 ; U15.D4@1101.45,-595.04 v1@1086.41,-580 ; U15.C4@1101.45,-564.96 v1@1086.41,-580 ; U15.C4@1101.45,-563.54 v1@1086.41,-548.5 ; U15.B4@1101.45,-533.46 v1@1086.41,-548.5 ; U15.B4@1101.45,-532.05 v1@1086.41,-517.01 ; U15.A4@1101.46,-501.97 v1@1086.41,-517.01
  Top Layer w15: v1(-1682.5,669.41) U6.6@-1657.5,669.41 ; D8.1@-1569,870 -1547,870 -1537,880 J4.8@-1537,966.14 ; v1(-1435,1035) D6.1@-1435,1062 ; v1(-1325,1035) D5.1@-1325,1062 ; v1(-1260,830) D7.1@-1233,830 ; v1@-875.59,1060 Q4.1@-875.59,1087.5 ; Q4.4@-824.41,1164 v1(-824.41,1190) ; Q5.4@-789,20.59 v1(-765.81,20.59) ; D12.1@-767,870 -745,870 -735,880 J3.8@-735,966.14 ; v1(-635,1035) D10.1@-635,1062 ; v1(-525,1035) D9.1@-525,1062 ; v1(-460,830) D11.1@-433,830 ; U9.2@411,480 v1(435,480) ; v1(465,385) U8.2@489,385
  Top Layer w16: v1(1145,-206.61) U17.4@1177,-206.61
  Top Layer w18: C8.2@-1690,-136 v1(-1690,-116) ; v1(-1607,-105) C33.2@-1607,-85 ; C34.2@-1412,-610 v1(-1412,-590) ; C9.2@-1378,-344 v1(-1378,-324) ; U4.4@-500,-525 v1(-500,-480) ; R83.2@-495,620 v1(-470,620) ; v1(-487.87,-889.97) CB111.2@-460,-890 ; v1(-487.87,-754.97) CB109.2@-460,-755 ; v1(-480,-673.97) CB110.2@-460,-674 ; R89.1@-446,-255 v1(-446,-236.5) R88.1@-446,-218 ; CB132.2@27.17,670.7 v1(27.17,700) J5.6@27.17,730.83 ; v1(114,-1285) C21.2@140,-1285 ; v1(143.97,-1082.88) CB115.2@144,-1055 ; v1(159.06,700) J5.12@159.06,730.83 ; C22.2@218,-1320 v1(237,-1320) ; v1(287.97,-1082.88) CB114.2@288,-1055 ; v1(420,-970.01) CB112.2@440,-970.04 ; v1(420,-762.87) CB113.2@440,-762.91 ; CB140.2@655,160 v1(655,179.5) ; C37.2@854,92 v1(873.5,92) ; v1(948.5,452.5) 951,455 C35.2@968,455 ; v1(950.52,-813.58) v1(950.52,-781.58) ; v1(951.02,-378.42) v1(951.02,-346.42) ; v1(974,350) 982.85,341.15 1004.85,341.15 R65.2@1005,341 ; v1(987,-425) R99.2@987,-404 ; C36.2@1022,304 v1(1022,286.5) 1022,269 CB135.2@1028,263 ; R101.2@1040,-725 v1(1061,-725) ; v1(1074,-399) CB137.2@1074,-375 ; R69.1@1080,452.5 v1(1099.5,452.5) ; v1(1134,-399) CB139.2@1134,-375 ; R106.2@1185,-351 v1(1185,-323.5) ; CB136.2@1210,135 v1(1229.5,135) ; v1(1212,-323.5) 1216.5,-319 C15.2@1235,-319 ; v1(1343,-991) R73.2@1343,-970 ; C40.2@1404,92 v1(1423.5,92) ; v1(1498.5,452.5) 1501,455 C38.2@1518,455 ; v1(1524,350) 1532.35,341.65 1553.35,341.65 R66.2@1554,341 ; C39.2@1572,304 v1(1572,286.5) 1572,269 CB134.2@1578,263 ; R71.1@1630,452.5 v1(1649.5,452.5)
  Top Layer w20: C41.2@-1662,480 v1(-1632,480) ; C41.2@-1662,510 v1(-1632,510) ; R82.2@-1655,586 v1(-1655,611) ; v1(-1605,-188.5) U12.2@-1605,-150 ; U13.2@-1415,-545 v1(-1415,-508) ; v1(-1407.5,275) U7.2@-1407.5,319 ; C11.2@-1310,402 -1309.64,402.36 v1(-1270.47,402.36) ; C31.2@-1085,980 v1(-1060,980) ; C32.2@-905,980 v1(-880,980) ; v1(-729.53,618.9) -695.31,618.9 C13.2@-695,619.21 ; v1(-729.53,697.64) C12.2@-697.36,697.64 ; v1(-684,-66) U20.2@-651,-66 ; v1(-653,50) C14.2@-630,50 ; C48.2@-287.5,-1228 v1(-287.5,-1204) ccw(c-266.25,-1204) v1(-245,-1204) ccw(c-223.75,-1204) v1@-202.5,-1204.07 ; -202.5,-1228 v1(-202.5,-1204) ccw(c-181.25,-1204) v1(-160,-1204) ccw(c-138.75,-1204) v1@-117.5,-1204.07 ; C49.2@-117.5,-1228 v1@-117.5,-1204.07 ; v1(1484,-147) U19.2@1484,-114 ; v1(1775,-1202.5) v1@1775.06,-1202.5 ; D1.2@1800,-1272.5 v1(1775,-1272.5) ; D1.2@1800,-1237.5 v1(1775,-1237.5) ; D1.2@1800,-1202.5 v1@1775.06,-1202.5 ; D1.2@1800,-1167.5 v1(1775,-1167.5) ; D1.2@1880,-1272.5 v1(1905,-1272.5) ; D1.2@1880,-1237.5 v1(1905,-1237.5) ; D1.2@1880,-1202.5 v1@1904.94,-1202.5 ; D1.2@1880,-1167.5 v1(1905,-1167.5) ; v1(1905,-1202.5) v1@1904.94,-1202.5 ; v1@-117.5,-1204.07 ccw(c-138.75,-1204) v1(-117.5,-1204) v1@-117.5,-1204.07 ; v1(1775,-1272.5) ccw(c1775,-1255) v1(1775,-1237.5) ; v1(1775,-1272.5) ccw(c1775,-1255) v1(1775,-1237.5) ; v1(1775,-1237.5) ccw(c1775,-1220) v1@1775.06,-1202.5 ; v1(1775,-1237.5) ccw(c1775,-1220) v1@1775.06,-1202.5 ; v1(1775,-1167.5) cw(c1775,-1185) v1@1775.06,-1202.5 ; v1(1775,-1167.5) cw(c1775,-1185) v1@1775.06,-1202.5 ; v1@1904.94,-1202.5 cw(c1905,-1185) v1(1905,-1167.5) ; v1@1904.94,-1202.5 cw(c1905,-1185) v1(1905,-1167.5) ; v1@1904.94,-1202.5 ccw(c1905,-1220) v1(1905,-1237.5) ; v1@1904.94,-1202.5 ccw(c1905,-1220) v1(1905,-1237.5) ; v1(1905,-1272.5) cw(c1905,-1255) v1(1905,-1237.5) ; v1(1905,-1272.5) cw(c1905,-1255) v1(1905,-1237.5)
  Top Layer w65: J6.2@1630,-900 M4.1@1825,-900 M4.1@1840,-900
  MidLayer1 w7: v1@136.25,321.93 136.25,331.45 144.58,339.78 ; v1@140,323.22 v1(141.73,321.48)
  MidLayer1 w18: -410,94.49 v1(-388,94.49) ; -343.25,280.25 v1(-314.96,251.97) ; -265,-1090 v1(-250,-1075) ; -194.44,342.7 v1(-173.23,321.48) -173.23,343.48 ; -94.49,344.96 v1(-94.49,314.96) -59.13,350.32 ; -80,-1080 v1(-65,-1065) -50,-1080 ; 65,-1088 v1(80,-1073) ; v1(420,-685) 435,-670 ; v1(420,-586) 435,-571 ; v1(420,-409) 435,-394 ; v1(420,-310) 435,-295 ; 435,-777.87 v1(420,-762.87) 435,-747.87
  MidLayer1 w20: 447.5,802 J8.1@447.5,880 ; 447.5,958 J8.1@447.5,880 ; 525.5,880 J8.1@447.5,880 ; 977,587.5 J8.3@1055,587.5 ; 1055,537.5 J8.3@1055,587.5 ; 1055,637.5 J8.3@1055,587.5 ; 1133,587.5 J8.3@1055,587.5 ; 1584.5,880 J8.2@1662.5,880 ; 1662.5,802 J8.2@1662.5,880 ; 1662.5,958 J8.2@1662.5,880
  MidLayer2 w18: -413,69.49 v1(-388,94.49) ; -413,119.49 v1(-388,94.49) ; -409.21,94.49 v1(-388,94.49) ; -265,-1090 v1(-250,-1075) ; -194.44,342.7 v1(-173.23,321.48) -173.23,343.48 ; 120.52,342.7 v1(141.73,321.48) ; 123.97,-1102.88 v1(143.97,-1082.88) 158.97,-1097.88 ; 141.73,343.48 v1(141.73,321.48) ; 162.95,342.7 v1(141.73,321.48) ; 272.97,-1097.88 v1(287.97,-1082.88) ; 410,-270 v1(395,-255) 416.21,-255
  MidLayer 3 w10.5: -423.36,94.49 v1(-388,94.49)
  MidLayer 3 w18: -265,-1090 v1(-250,-1075) -250,-1096.21 ; -80,-1080 v1(-65,-1065) -50,-1080 ; 65,-1088 v1(80,-1073) ; 141.73,356.48 v1(141.73,321.48) 162.95,342.7
  MidLayer 4 w10: v1(877,-1315) 877,-1372.37 896.55,-1391.92 ccw(c910.47,-1378) 930.16,-1378 ; 930.16,-1380 930.16,-1280
  MidLayer 4 w10.5: -464.49,94.49 v1(-388,94.49)
  MidLayer 4 w18: -265,-1090 v1(-250,-1075) ; -80,-1080 v1(-65,-1065) -50,-1080 ; 65,-1088 v1(80,-1073) ; 410,-270 v1(395,-255) 416.21,-255
  Bottom Layer w8: v1@459.5,382.2 462.29,385 v1(465,385)
  Bottom Layer w10: v1(283.46,62.99) 297.56,48.9 311.1,48.9 R60A.2@315,45 ; CB72.2@432,382.2 v1@459.5,382.2 ; J6.2@1630,-932.5 cw(c1630,-900) J6.2@1630,-867.5 ; 1005,625 cw(c1005,650) 1026.65,637.5 1005,625 ; J8.3@1018.35,600 ccw(c1040,587.5) 1040,562.5 1070,562.5 ccw(c1070,587.5) 1070,612.5 1040,612.5 J8.3@1018.35,600
  Bottom Layer w10.5: C77.2@765,-1365 v1(793,-1365) ; v1(1102,-1380) 1130.75,-1380
  Bottom Layer w12: CB69.2@-360,-696.5 v1(-360,-685.5) CB40.2@-360,-674.5 ; R45.2@-42,-826 -41.89,-826.11 -41.89,-850.87 v1(-41.77,-850.98) ; R44.2@259,-824 R44.2@260,-825 ; v1(1003,-1315) 1004.62,-1315 1007.62,-1318 1009,-1318 1024,-1333 1024,-1337.97 1031.03,-1345 1046,-1345 1050,-1349 R96.2@1050,-1350
  Bottom Layer w18: v1(-325.03,-1074.96) R75.2@-325,-1055 ; CB102.2@-294,54 -294,42.03 v1(-283.46,31.5) ; CB102.2@-293,53 CB102.2@-292,52 ; CB88.2@-218.87,126.68 CB88.2@-218.87,127.59 ; CB100.2@-195,286.6 -195,299.71 v1(-173.23,321.48) ; v1(-31.5,-94.49) CB94.2@-23.98,-102 ; v1(-31.5,157.48) -19.02,145 -6,145 CB119.2@0,139 ; v1(31.5,-62.99) v1(62.99,-62.99) ; v1(239.97,-823.97) R44.2@259,-824 ; CB130.2@920,219 940.5,219 v1@947.5,212 ; v1(923.5,-1315) v1(971.5,-1315) v1(1003,-1315) ; CB130.2@930,231 947.5,231 947.5,126.5 C58.2@937.6,126.5 ; C25.2@1078,-700 1078,-681.49 v1(1085,-674.49) ; CB131.2@1470,219 1490.5,219 v1@1497.5,212 ; CB131.2@1470,231 1497.5,231 1497.5,126.5 C57.2@1487.6,126.5
  Bottom Layer w20: v1(-1270.47,520.47) -1270,520 C30.2@-1245,520 ; C29.2@-1208,678.27 -1179.84,678.27 v1(-1179.53,677.95) ; C28.2@-980,700 -980,720 v1(-970.47,729.53) ; v1(-830,600) C27.2@-795,600 ; v1(-820.47,638.58) -795.31,638.58 C26.2@-795,638.27 ; v1(-446,-236.5) CB129.2@-420.5,-236.5 ; CB90.2@-283.5,-152 -283.5,-157.98 -283.46,-158.01 v1(-283.46,-188.98) ; CB99.2@-66.61,-302.5 -66.61,-287.09 v1(-62.99,-283.46) ; v1(-31.5,-62.99) v1(-31.5,-31.5) -31.5,0 v1(-31.5,31.5) ; v1(62.99,-283.46) 62.99,-303.5 CB122.2@64.49,-305 ; v1(141.73,321.48) 145.58,317.63 145.58,292.92 CB124.2@149,289.5 ; CB120.2@230.79,0 CB98.2@282,0 ; v1(251.97,-62.99) 253.98,-65 CB127.2@332,-65 ; v1(876,-1278) 876,-1314 v1(877,-1315) ; CB138.2@940,-1291 v1(940,-1276) ; v1(1003,-1315) 1004,-1314 v1(1004,-1278)
  Bottom Layer w24: v1@-157.48,-29.5 v1(-157.48,31.5)
  Bottom Layer w30: CB121.2@-50,0 -31.5,0 v1(0,0)
  other v1: 410,-1380 460,-1380 510,-1380 1370,-1380 1420,-1380 1470,-1380 -60,-1365 -267.5,-1355 -147.5,-1355 410,-1290 460,-1290 510,-1290 1370,-1290 1420,-1290 1470,-1290 -50,-1280 15,-1280 80,-1280 940,-1235 -50,-1200 15,-1200 80,-1200 940,-1166.5 700,-1138 755,-1138 1070,-1138 1125,-1138 -655,-1105 -555,-1105 700,-1095 755,-1095 1070,-1095 1125,-1095 -425,-1085 -655,-1060 -555,-1060 700,-1052 755,-1052 1070,-1052 1125,-1052 -655,-1015 -555,-1015 555,-990 600,-990 645,-990 1155,-990 1245,-990 -1575,-985 -425,-985 1200,-900 555,-890 600,-890 645,-890 1155,-890 1245,-890 -1575,-825 860.52,-813.58 890.52,-813.58 920.52,-813.58 -356.73,-787.99 860.52,-781.58 890.52,-781.58 920.52,-781.58 1332,-728.5 1364,-728.5 1300,-728.35 -547.5,-718.5 -509.5,-718.5 1332.02,-696.63 1364.02,-696.63 1300.02,-696.48 -325.24,-693.5 -547.5,-681.5 -509.5,-681.5 104.76,-662.01 1085,-642.99 915,-640 1255,-640 449,-636 491,-636 -425,-635 1085,-611.5 449,-599 491,-599 1085,-580 555,-575 655,-575 136.26,-567.52 1085,-548.5 -425,-535 555,-530 655,-530 420,-527.5 915,-520 1255,-520 1085,-517.01 1085,-485.51 555,-485 655,-485 1300,-463.35 1332,-463.5 1364,-463.5 31.5,-456.69 515,-440 615,-440 1300,-431.35 1332,-431.5 1364,-431.5 -425,-410 515,-395 615,-395 861.02,-378.42 891.02,-378.42 921.02,-378.42 515,-350 615,-350 861.02,-346.42 891.02,-346.42 921.02,-346.42 -220.47,-314.96 -380,-310 -682.92,-298 920,-260 965,-260 1010,-260 31.5,-220.47 965,-215 1010,-215 1334,-213.5 1376,-213.5 1334,-176.5 1376,-176.5 930,-170 965,-170 1010,-170 0,-125.98 846.5,-103.5 1380,-84 656.5,-61 693.5,-61 883.5,-60 1205,-57 1245,-57 1288,-57 656.5,-19 693.5,-19 846.5,-19.5 -1700,-5 -1655,-5 -1610,-5 -62.99,0 220.47,0 251.97,0 -668.5,89.5 -631.5,89.5 -1697,95 -1655,95 -1610,95 -314.96,125.98 0,125.98 220.47,125.98 -668.5,173.5 -631.5,173.5 947.5,207 1497.5,207 94.49,220.47 220.47,220.47 314.96,220.47 947.5,233 1497.5,233 -668.5,249.5 -631.5,249.5 -31.5,251.97 765,280 855,280 1315,280 1405,280 1169.73,315.28 -668.5,333.5 -631.5,333.5 -476,362 -434,362 765,367.5 855,367.5 1315,370 1405,370 -1538.29,388 -476,396.5 -434,396.5 -910,465 -1090,470 187,497 -1045,510 204.5,522 -1445,525 -1405,525 -1365,525 222,547 -1090,550 -1000,550 -910,560 -387.5,579 -237.5,579 -1045,595 -955,595 -1445,615 -1405,615 -1365,615 -1090,640 -1000,640 -910,640 220,724.33 -336.5,734 -336.5,764.33 220,764.33 -336.5,878.83 -336.5,916.83 217.5,985.13 217.5,1023.13 -1060,1025 -880,1025 -876.59,1060 -324.5,1093.33 -336.5,1131.33 -340,1260 220,1260 -340,1290 220,1290
IN51_6: J10.6 U1.B9 | length 771.1
  Top Layer w5: v1(-543,-40) -490,-40 -460,-70 -410,-70 -371.5,-31.5 -283.47,-31.5 U1.B9@-267.72,-47.24
  MidLayer 4 w5: J10.6@-865,-350 -830,-315 -800,-315 -543,-58 v1(-543,-40)
INTVCC2_10: CB137.1 U15.A2 U15.D5 U15.F6 | length 438.8
  Top Layer w6: U15.D5@1132.24,-595.75 v1(1147.99,-580) ; v1(1163.74,-683.74) U15.F6@1163.74,-658.74
  Top Layer w12: U15.A2@1037.76,-501.26 1037.76,-475
  Top Layer w25: 1037.76,-475 CB137.1@1073.11,-439.64
  MidLayer1 w6: v1(1074,-435) 1100,-435 1165,-500 1165,-562.99 v1(1147.99,-580) 1163.74,-595.75 v1(1163.74,-683.74)
INTVCC_10: CB138.1 U16.1 U16.5 U16.8 U16.29 | length 317.6
  Top Layer w9: U16.29@947.5,-1314.37 947.5,-1327.66 949.84,-1330
  Top Layer w11: v1@853,-1362.5 861.45,-1362.5 ; v1@855.47,-1368.47 861.45,-1362.5 ; U16.1@871.1,-1362.5 861.45,-1362.5 ; v1(949.84,-1378) U16.5@949.84,-1352 949.84,-1330 ; U16.8@1008.9,-1362.5 1025,-1362.5 v1@1025.05,-1362.5 ; 1016.55,-1362.5 v1@1022.53,-1368.47
  MidLayer 4 w18: v1(949.84,-1378) 972.84,-1355 1014,-1355 v1(1025,-1366)
  Bottom Layer w18: v1(853,-1366) 864,-1355 CB138.1@941,-1355 ; v1(949.84,-1378) CB138.1@949.84,-1358
IO1-0: J1.1 U1.N18 | length 2623.3
  Top Layer w5: U1.N18@78.74,236.22 v1(94.49,251.97)
  MidLayer 4 w5: J1.1@-1810.63,951.77 -1682.4,1080 -1181.67,1080 -1168.5,1066.83 -1168.5,698.5 -1160,690 -1160,575 -1070,485 -110,485 35,340 35,311.46 v1(94.49,251.97)
IO1-1: J1.3 U1.M20 | length 2668.1
  Top Layer w5: v1(-47.5,575) -47.5,467.5 47.24,372.76 U1.M20@47.24,299.21
  MidLayer 3 w5: J1.3@-1810.63,873.03 -1770,913.66 -1770,978 -1593,1155 -336.84,1155 -245,1063.16 -245,747.5 -137.5,640 -95,640 -47.5,592.5 v1(-47.5,575)
IO1-2: J1.4 U1.M19 | length 2817
  Top Layer w5: v1(-27.5,540) -27.5,467.5 62.99,377.01 62.99,283.46 U1.M19@47.24,267.72
  MidLayer 3 w5: J1.4@-1889.37,873.03 -1850,912.4 -1850,975 -1825,1000 -1773,1000 -1603,1170 -325,1170 -230,1075 -230,755 -130,655 -90,655 -27.5,592.5 v1(-27.5,540)
IO1-3: J1.5 U1.L20 | length 2634.5
  Top Layer w5: v1(-87.5,575) -87.5,467.5 15.75,364.25 U1.L20@15.75,299.21
  MidLayer 3 w5: J1.5@-1810.63,794.29 -1776.97,794.29 -1730,841.26 -1730,968 -1573,1125 -417.5,1125 -275,982.5 -275,732.5 -152.5,610 -110,610 -87.92,587.92 -87.92,575.42 v1(-87.5,575)
IO1-4: J1.6 U1.L19 | length 2768.8
  Top Layer w5: v1(-67.5,540) -67.5,467.5 31.5,368.5 31.5,283.46 U1.L19@15.75,267.72
  MidLayer 3 w5: J1.6@-1889.37,794.29 -1850,833.66 -1785,833.66 -1750,868.66 -1750,973 -1583,1140 -410,1140 -260,990 -260,740 -145,625 -105,625 -67.5,587.5 v1(-67.5,540)
IO1-5: J1.7 U1.K19 | length 2657.1
  Top Layer w5: v1(-127.5,575) -127.5,467.5 -31.5,371.5 -31.5,283.46 U1.K19@-15.75,267.72
  MidLayer 3 w5: J1.7@-1810.63,715.55 -1759.45,715.55 -1690,785 -1690,958 -1553,1095 -432.5,1095 -305,967.5 -305,717.5 -162.5,575 v1(-127.5,575)
IO1-6: J1.8 U1.K18 | length 2794.2
  Top Layer w5: v1(-107.5,540) -107.5,467.5 0,360 0,251.97 U1.K18@-15.75,236.22
  MidLayer 3 w5: J1.8@-1889.37,715.55 -1850,754.92 -1775.08,754.92 -1710,820 -1710,963 -1563,1110 -425,1110 -290,975 -290,725 -160,595 -115,595 -107.5,587.5 v1(-107.5,540)
IO1-7: J1.9 U1.J19 | length 1959.9
  Top Layer w5: v1(-215,510) -62.99,357.99 -62.99,283.46 U1.J19@-47.24,267.72
  MidLayer 3 w5: J1.9@-1810.63,636.81 -1641.81,636.81 -1600,595 -1075,595 -1056.5,576.5 -804,576.5 -787.5,560 -265,560 v1(-215,510)
IO1-8: J1.10 U1.J20 | length 2693.9
  Top Layer w5: v1(-147.5,540) -147.5,467.5 -47.24,367.24 U1.J20@-47.24,299.21
  MidLayer 3 w5: J1.10@-1889.37,636.81 -1850,676.18 -1748.82,676.18 -1670,755 -1670,953 -1543,1080 -440,1080 -320,960 -320,710 -150,540 v1(-147.5,540)
IO1-9: J1.11 U1.G20 | length 1856
  Top Layer w5: v1(-295,510) -110.24,325.24 U1.G20@-110.24,299.21
  MidLayer 3 w5: J1.11@-1810.63,558.07 -1508.07,558.07 -1440,490 -850,490 -810,530 -315,530 v1(-295,510)
IO1-10: J1.12 U1.H20 | length 1983.1
  Top Layer w5: v1(-255,510) -78.74,333.74 U1.H20@-78.74,299.21
  MidLayer 3 w5: J1.12@-1889.37,558.07 -1850,597.44 -1672.44,597.44 -1655,580 -1080,580 -1030,530 -826.98,530 -811.98,545 -290,545 v1(-255,510)
IO1-11: J1.13 U1.E19 | length 1833.2
  Top Layer w5: v1(-335,510) -188.98,363.98 -188.98,283.46 U1.E19@-173.23,267.72
  MidLayer 3 w5: J1.13@-1810.63,484.37 J1.13@-1810.63,479.33 -1689.33,479.33 -1670,460 -1255,460 -1237.5,442.5 -877.5,442.5 -810,510 v1(-335,510)
IO1-12: J1.15 U1.N15 | length 2255.4
  Top Layer w5: U1.N15@78.74,141.73 v1(94.49,157.48)
  MidLayer 3 w5: J1.15@-1810.63,400.59 -1650.59,400.59 -1618.68,432.5 -1510,432.5 -1500,422.5 -1237.5,422.5 -1220,405 -895,405 -809.02,490.98 -40,490.98 110.24,340.75 110.24,173.23 v1(94.49,157.48)
IO1-13: J1.16 U1.M15 | length 2306.8
  Top Layer w5: U1.M15@47.24,141.73 v1(62.99,157.48)
  MidLayer 3 w5: J1.16@-1889.37,400.59 -1850,361.22 -1253.78,361.22 -1223.5,391.5 -888.5,391.5 -804.02,475.98 -45,475.98 78.74,352.24 78.74,173.23 v1(62.99,157.48)
IO1-14: J1.17 U1.M17 | length 2127.8
  Top Layer w5: U1.M17@47.24,204.72 v1(62.99,220.47)
  MidLayer 3 w5: J1.17@-1810.63,321.85 -1807.48,325 -885,325 -749.02,460.98 -50,460.98 47.24,363.74 47.24,236.22 v1(62.99,220.47)
IO1-15: J1.18 U1.L16 | length 2247.2
  Top Layer w5: U1.L16@15.75,173.23 v1(31.5,188.98)
  MidLayer 3 w5: J1.18@-1889.37,321.85 -1850,282.48 -1792.5,282.48 -1764.98,310 -880,310 -744.02,445.98 -55,445.98 31.5,359.49 31.5,284.21 15,267.72 15,205.47 v1(31.5,188.98)
IO1-16: J1.19 U1.L15 | length 2171
  Top Layer w5: U1.L15@15.75,141.73 v1(31.5,157.48)
  MidLayer 3 w5: J1.19@-1810.63,243.11 -1758.74,295 -875,295 -739.02,430.98 -60,430.98 15.75,355.24 15.75,290.75 5,280 5,183.98 v1(31.5,157.48)
IO1-17: J1.20 U1.K14 | length 2280.8
  Top Layer w5: v1(-31.5,125.98) U1.K14@-15.75,110.24
  MidLayer 3 w5: J1.20@-1889.37,243.11 -1850,203.74 -1796.26,203.74 -1741.5,258.5 -891.5,258.5 -755,395 -720,395 -699.02,415.98 -65,415.98 0,350.98 0,300 -5,295 -5,152.48 v1(-31.5,125.98)
IO1-18: J1.21 U1.K16 | length 2102.5
  Top Layer w5: v1(-31.5,188.98) U1.K16@-15.75,173.23
  MidLayer 3 w5: J1.21@-1810.63,164.37 -1731.5,243.5 -886.5,243.5 -750,380 -340,380 -319.02,400.98 -70,400.98 -31.5,362.48 -31.5,284.21 -15,267.72 -15,205.47 v1(-31.5,188.98)
IO1-19: J1.22 U1.K17 | length 2151.9
  Top Layer w5: v1(-31.5,220.47) U1.K17@-15.75,204.72
  MidLayer 3 w5: J1.22@-1889.37,164.37 -1850,125 -1800,125 -1696.5,228.5 -846.5,228.5 -720,355 -500,355 -490.5,345.5 -354.5,345.5 -314.02,385.98 -75.98,385.98 -47.24,357.24 -47.24,236.22 v1(-31.5,220.47)
IO1-20: J1.23 U1.J18 | length 1993.7
  Top Layer w5: v1(-62.99,251.97) U1.J18@-47.24,236.22
  MidLayer 3 w5: J1.23@-1810.63,85.63 -1682.76,213.5 -841.5,213.5 -740,315 -515,315 -499.5,330.5 -349.5,330.5 -309.02,370.98 -85.98,370.98 -62.99,347.99 v1(-62.99,251.97)
IO1-21: J1.24 U1.J15 | length 2163.6
  Top Layer w5: v1(-62.99,157.48) U1.J15@-47.24,141.73
  MidLayer 3 w5: J1.24@-1889.37,85.63 -1850,46.26 -1798.74,46.26 -1700,145 -890,145 -735,300 -507.5,300 -492,315.5 -344.5,315.5 -304.02,355.98 -110.98,355.98 -78.74,323.74 -78.74,173.23 v1(-62.99,157.48)
IO1-22: J1.25 U1.H18 | length 1940.7
  Top Layer w5: v1(-94.49,251.97) U1.H18@-78.74,236.22
  MidLayer 3 w5: J1.25@-1810.63,6.89 -1687.52,130 -885,130 -730,285 -500,285 -484.5,300.5 -339.5,300.5 -300.84,339.16 -134.16,339.16 -110.24,315.24 -110.24,283.46 ccw(c-94.49,283.46) -98.83,268.33 cw(c-100.48,262.56) -94.48,262.56 v1(-94.49,251.97)
IO1-23: J1.27 U1.G18 | length 1854.8
  Top Layer w5: v1(-125.98,251.97) U1.G18@-110.24,236.22
  MidLayer 3 w5: J1.27@-1810.63,-71.85 -1678.78,60 -1595,60 -1580,75 -900,75 -742,233 -302,233 -267.28,267.72 -157.48,267.72 cw(c-157.48,251.97) -142.34,256.31 ccw(c-136.57,257.96) -136.57,251.96 v1(-125.98,251.97)
IO1-24: J1.28 U1.H15 | length 2083.1
  Top Layer w5: v1(-94.49,157.48) U1.H15@-78.74,141.73
  MidLayer 3 w5: J1.28@-1889.37,-71.85 -1850,-32.48 -1797.48,-32.48 -1690,75 -1600,75 -1560,115 -880,115 -727.5,267.5 -337.5,267.5 -305.79,299.21 -157.48,299.21 cw(c-157.48,283.46) -141.73,283.46 ccw(c-125.99,283.46) -125.99,267.72 cw(c-125.98,251.97) -110.24,251.97 -110.24,173.23 v1(-94.49,157.48)
IO1-25: J1.29 U1.G17 | length 1860.6
  Top Layer w5: v1(-125.98,220.47) U1.G17@-110.24,204.72
  MidLayer 3 w5: J1.29@-1810.63,-150.59 -1700.04,-40 -1595,-40 -1510,45 -890,45 -731,204 -265.72,204 -265,204.72 -141.73,204.72 v1(-125.98,220.47)
IO1-26: J1.30 U1.F17 | length 1920.9
  Top Layer w5: v1(-157.48,220.47) U1.F17@-141.73,204.72
  MidLayer 3 w5: J1.30@-1889.37,-150.59 -1850,-111.22 -1801.22,-111.22 -1715,-25 -1600,-25 -1515,60 -895,60 -736,219 -286,219 -268.78,236.22 -173.23,236.22 v1(-157.48,220.47)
